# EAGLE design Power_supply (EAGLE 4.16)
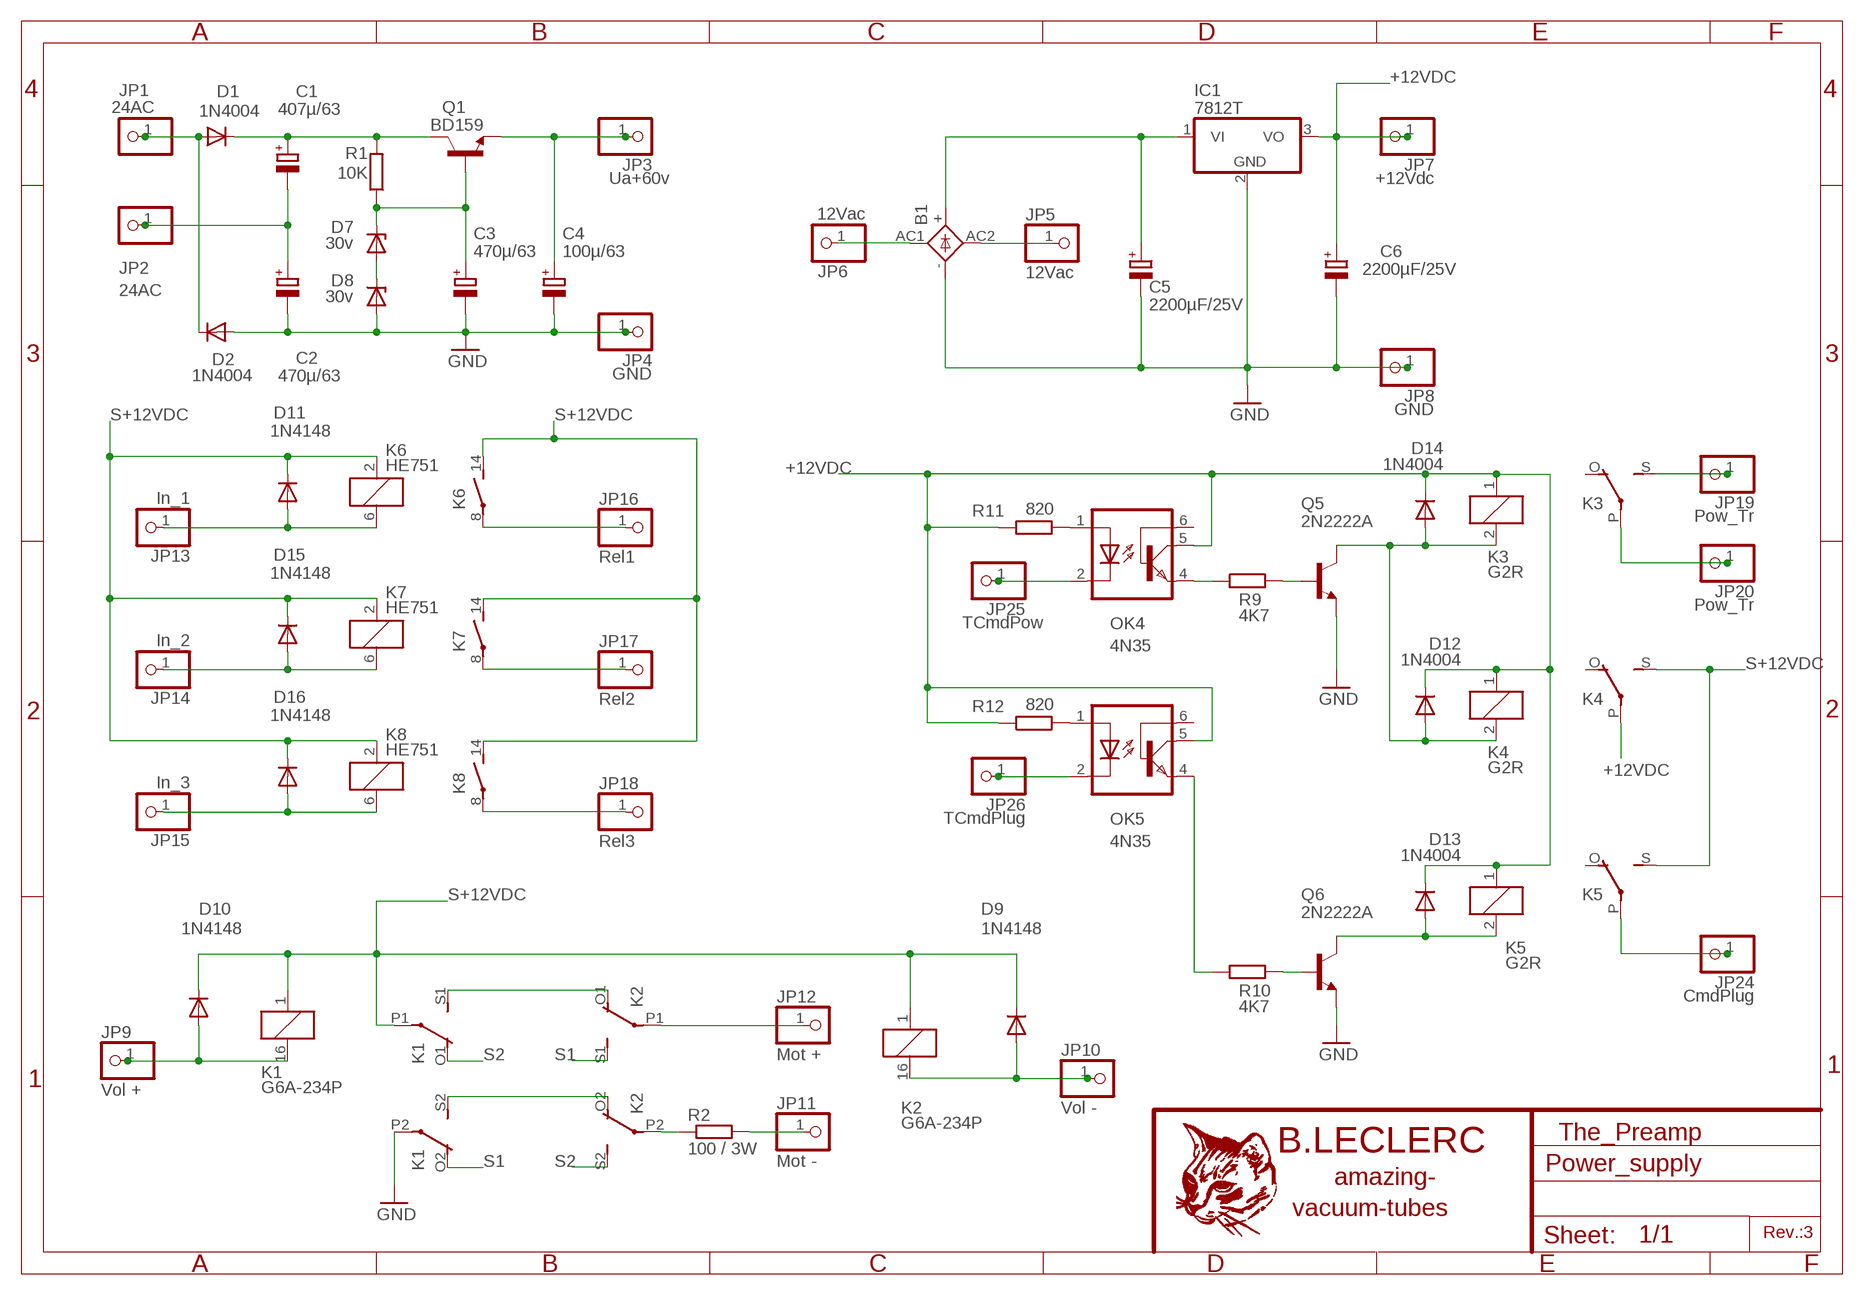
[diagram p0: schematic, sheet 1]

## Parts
B1  FB32  [FB32]
C1  407µ/63  CPOL-EUE7.5-16  [E7,5-16]
C2  470µ/63  CPOL-EUE7.5-16  [E7,5-16]
C3  470µ/63  CPOL-EUE7.5-16  [E7,5-16]
C4  100µ/63  CPOL-EUE5-10.5  [E5-10,5]
C5  2200µF/25V  CPOL-EUE7.5-18  [E7,5-18]
C6  2200µF/25V  CPOL-EUE7.5-18  [E7,5-18]
D1  1N4004  [DO41-10]
D2  1N4004  [DO41-10]
D7  30v  ZENER-DIODEZD-7.5  [ZDIO-7.5]
D8  30v  ZENER-DIODEZD-7.5  [ZDIO-7.5]
D9  1N4148  [DO35-10]
D10  1N4148  [DO35-10]
D11  1N4148  [DO35-10]
D12  1N4004  [DO41-10]
D13  1N4004  [DO41-10]
D14  1N4004  [DO41-10]
D15  1N4148  [DO35-10]
D16  1N4148  [DO35-10]
IC1  7812T  [TO220H]
JP1  24AC  PINHD-1X1  [1X01]
JP2  24AC  PINHD-1X1  [1X01]
JP3  Ua+60v  PINHD-1X1  [1X01]
JP4  GND  PINHD-1X1  [1X01]
JP5  12Vac  PINHD-1X1  [1X01]
JP6  12Vac  PINHD-1X1  [1X01]
JP7  +12Vdc  PINHD-1X1  [1X01]
JP8  GND  PINHD-1X1  [1X01]
JP9  Vol +  PINHD-1X1  [1X01]
JP10  Vol -  PINHD-1X1  [1X01]
JP11  Mot -  PINHD-1X1  [1X01]
JP12  Mot +  PINHD-1X1  [1X01]
JP13  In_1  PINHD-1X1  [1X01]
JP14  In_2  PINHD-1X1  [1X01]
JP15  In_3  PINHD-1X1  [1X01]
JP16  Rel1  PINHD-1X1  [1X01]
JP17  Rel2  PINHD-1X1  [1X01]
JP18  Rel3  PINHD-1X1  [1X01]
JP19  Pow_Tr  PINHD-1X1  [1X01]
JP20  Pow_Tr  PINHD-1X1  [1X01]
JP24  CmdPlug  PINHD-1X1  [1X01]
JP25  TCmdPow  PINHD-1X1  [1X01]
JP26  TCmdPlug  PINHD-1X1  [1X01]
K1  G6A-234P  [G6A-234P]
K2  G6A-234P  [G6A-234P]
K3  G2R  [G2R]
K4  G2R  [G2R]
K5  G2R  [G2R]
K6  HE751  [HE751]
K7  HE751  [HE751]
K8  HE751  [HE751]
OK4  4N35  [DIL06]
OK5  4N35  [DIL06]
Q1  BD159  MJE182  [TO225AA]
Q5  2N2222A  [TO18]
Q6  2N2222A  [TO18]
R1  10K  R-EU_0207/10  [0207/10]
R2  100 / 3W  R-EU_0613/15  [P0613/15]
R9  4K7  R-EU_0309/10  [0309/10]
R10  4K7  R-EU_0309/10  [0309/10]
R11  820  R-EU_0309/10  [0309/10]
R12  820  R-EU_0309/10  [0309/10]

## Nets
+12VDC: C6.+ D12.C D13.C D14.C IC1.3(VO) JP7.1 K3.1 K4.1 K4.P(2:P) K5.1 OK4.5(COL) OK5.5(COL) R11.1 R12.1
GND: B1.- C2.- C3.- C4.- C5.- C6.- D2.A D8.A IC1.2(GND) JP4.1 JP8.1 K1.P2(3:P) Q5.1(E) Q6.1(E)
N$1: D1.A D2.C JP1.1
N$2: C1.- C2.+ JP2.1
N$3: C1.+ D1.C Q1.2(C) R1.2
N$4: D7.A D8.C
N$5: C3.+ D7.C Q1.3(B) R1.1
N$6: B1.AC2 JP5.1
N$7: C4.+ JP3.1 Q1.1(E)
N$8: B1.AC1 JP6.1
N$9: B1.+ C5.+ IC1.1(VI)
N$10: K1.S1(2:S) K2.O1(2:O)
N$11: K1.S2(3:S) K2.O2(3:O)
N$12: JP12.1 K2.P1(2:P)
N$13: D10.A JP9.1 K1.16
N$14: K2.P2(3:P) R2.1
N$15: D9.A JP10.1 K2.16
N$16: JP11.1 R2.2
N$17: D11.A JP13.1 K6.6
N$18: JP16.1 K6.8(2:P)
N$19: JP17.1 K7.8(2:P)
N$20: JP18.1 K8.8(2:P)
N$21: D15.A JP14.1 K7.6
N$22: D16.A JP15.1 K8.6
N$32: JP19.1 K3.S(2:S)
N$35: JP24.1 K5.P(2:P)
N$37: JP20.1 K3.P(2:P)
N$38: D12.A D14.A K3.2 K4.2 Q5.3(C)
N$39: OK4.1(A) R11.2
N$40: D13.A K5.2 Q6.3(C)
N$41: OK5.1(A) R12.2
N$42: Q5.2(B) R9.2
N$43: OK4.4(EMI) R9.1
N$44: OK5.4(EMI) R10.1
N$45: Q6.2(B) R10.2
N$47: JP25.1 OK4.2(C)
N$48: JP26.1 OK5.2(C)
S1: K1.O2(3:O) K2.S1(2:S)
S2: K1.O1(2:O) K2.S2(3:S)
S+12VDC: D9.C D10.C D11.C D15.C D16.C K1.1 K1.P1(2:P) K2.1 K4.S(2:S) K5.S(2:S) K6.2 K6.14(2:S) K7.2 K7.14(2:S) K8.2 K8.14(2:S)
Unconnected: K3.O(2:O) K4.O(2:O) K5.O(2:O) OK4.6(BAS) OK5.6(BAS)

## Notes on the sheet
- The_Preamp
- Rev.:3

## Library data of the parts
B1 = rectifier:FB32: FAGOR RECTIFIER grid 1 x 10,2 x 7,5 mm
C1-C6 = rcl:CPOL-EU: POLARIZED CAPACITOR, European symbol
D1 D2 D12-D14 = diode:1N4004: DIODE
D7 D8 = diode:ZENER-DIODE: Z-Diode
D9-D11 D15 D16 = diode:1N4148: DIODE
IC1 = linear:78*: Positive VOLTAGE REGULATOR Source: http://cache.national.com/ds/LM/LM78L05.pdf http://www.fairchildsemi.com/ds/LM/LM7805.pdf
JP1-JP20 JP24-JP26 = pinhead:PINHD-1X1: PIN HEADER
K1 K2 = relay:G6A-234P: RELAY 2 x switch, 0.3 A/125 V AC, 1 A/30 V DC, Omron
K3-K5 = relay:G2R: RELAY 1 x switch, Omron
K6-K8 = relay:HE751: RELAY reed, 1 x norm. open, Hamlin
OK4 OK5 = optocoupler:4N35: MOTOROLA OPTO COUPLER
Q1 = transistor-npn:MJE182*: NPN Transistor
Q5 Q6 = transistor-npn:2N2222*: NPN Transistor
R1 R2 R9-R12 = rcl:R-EU_: RESISTOR, European symbol

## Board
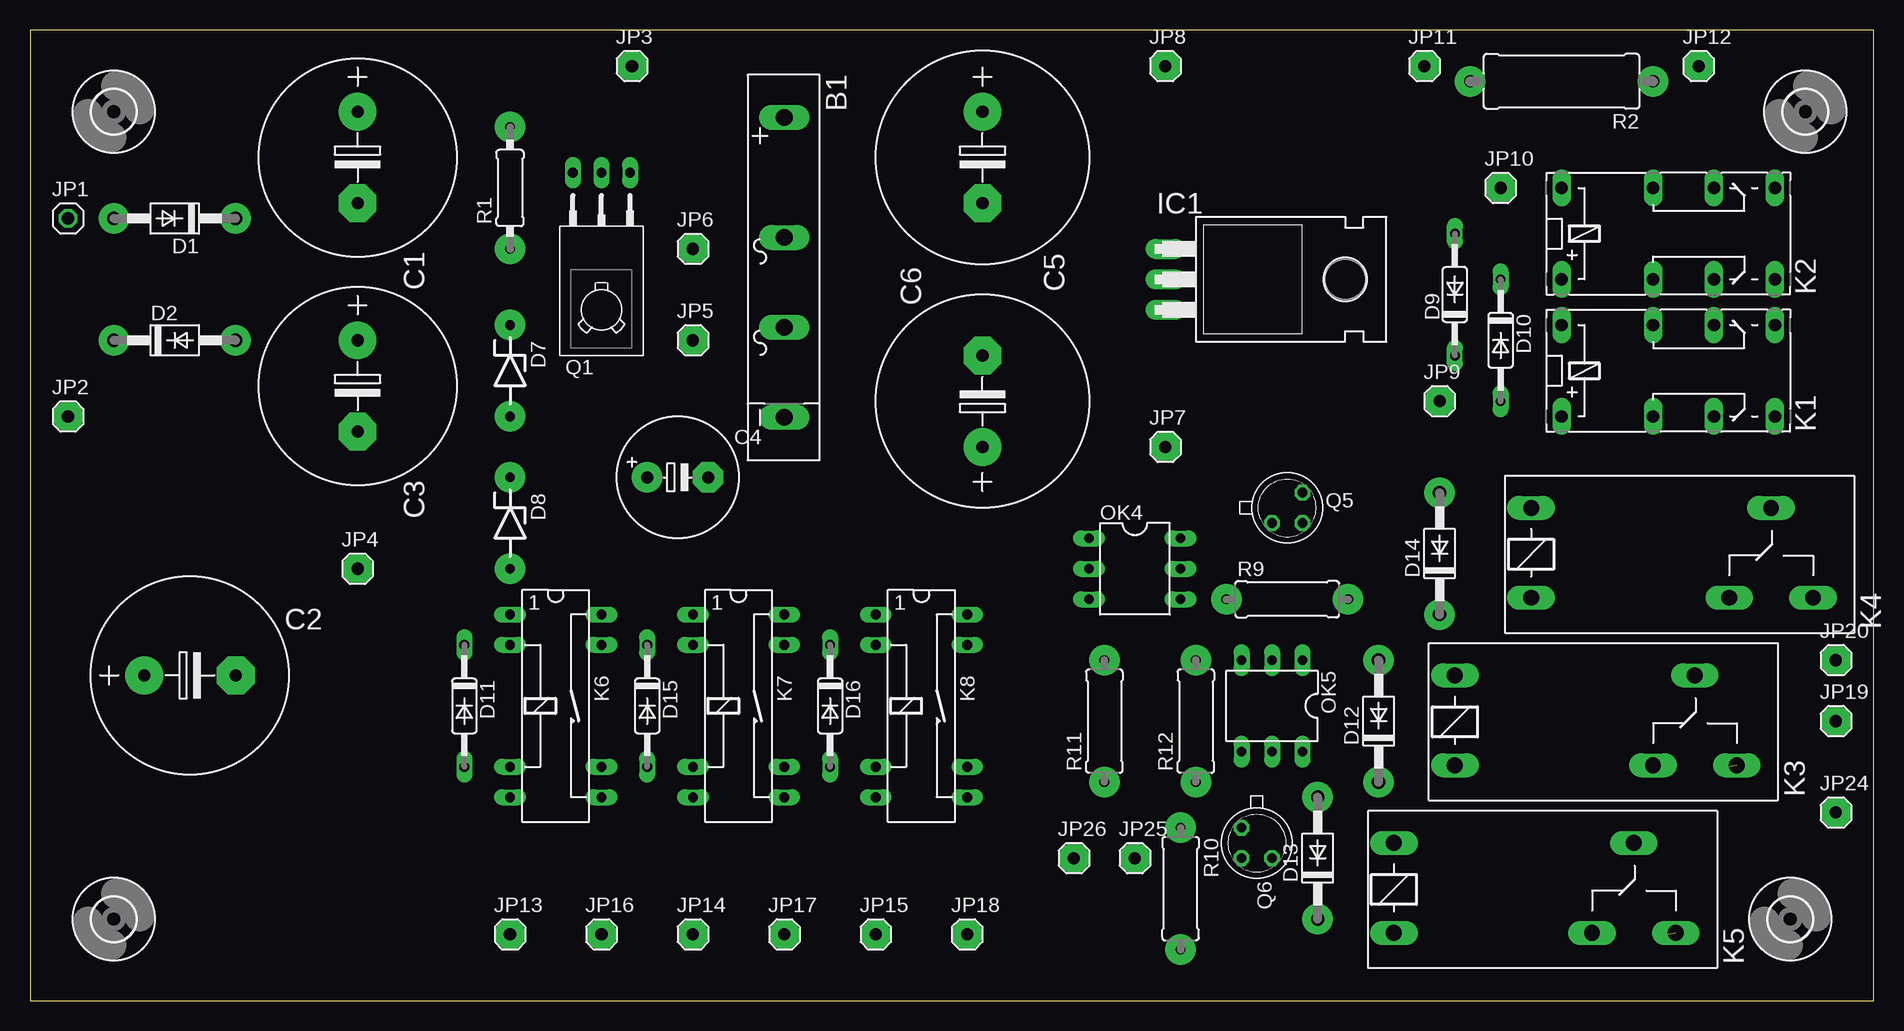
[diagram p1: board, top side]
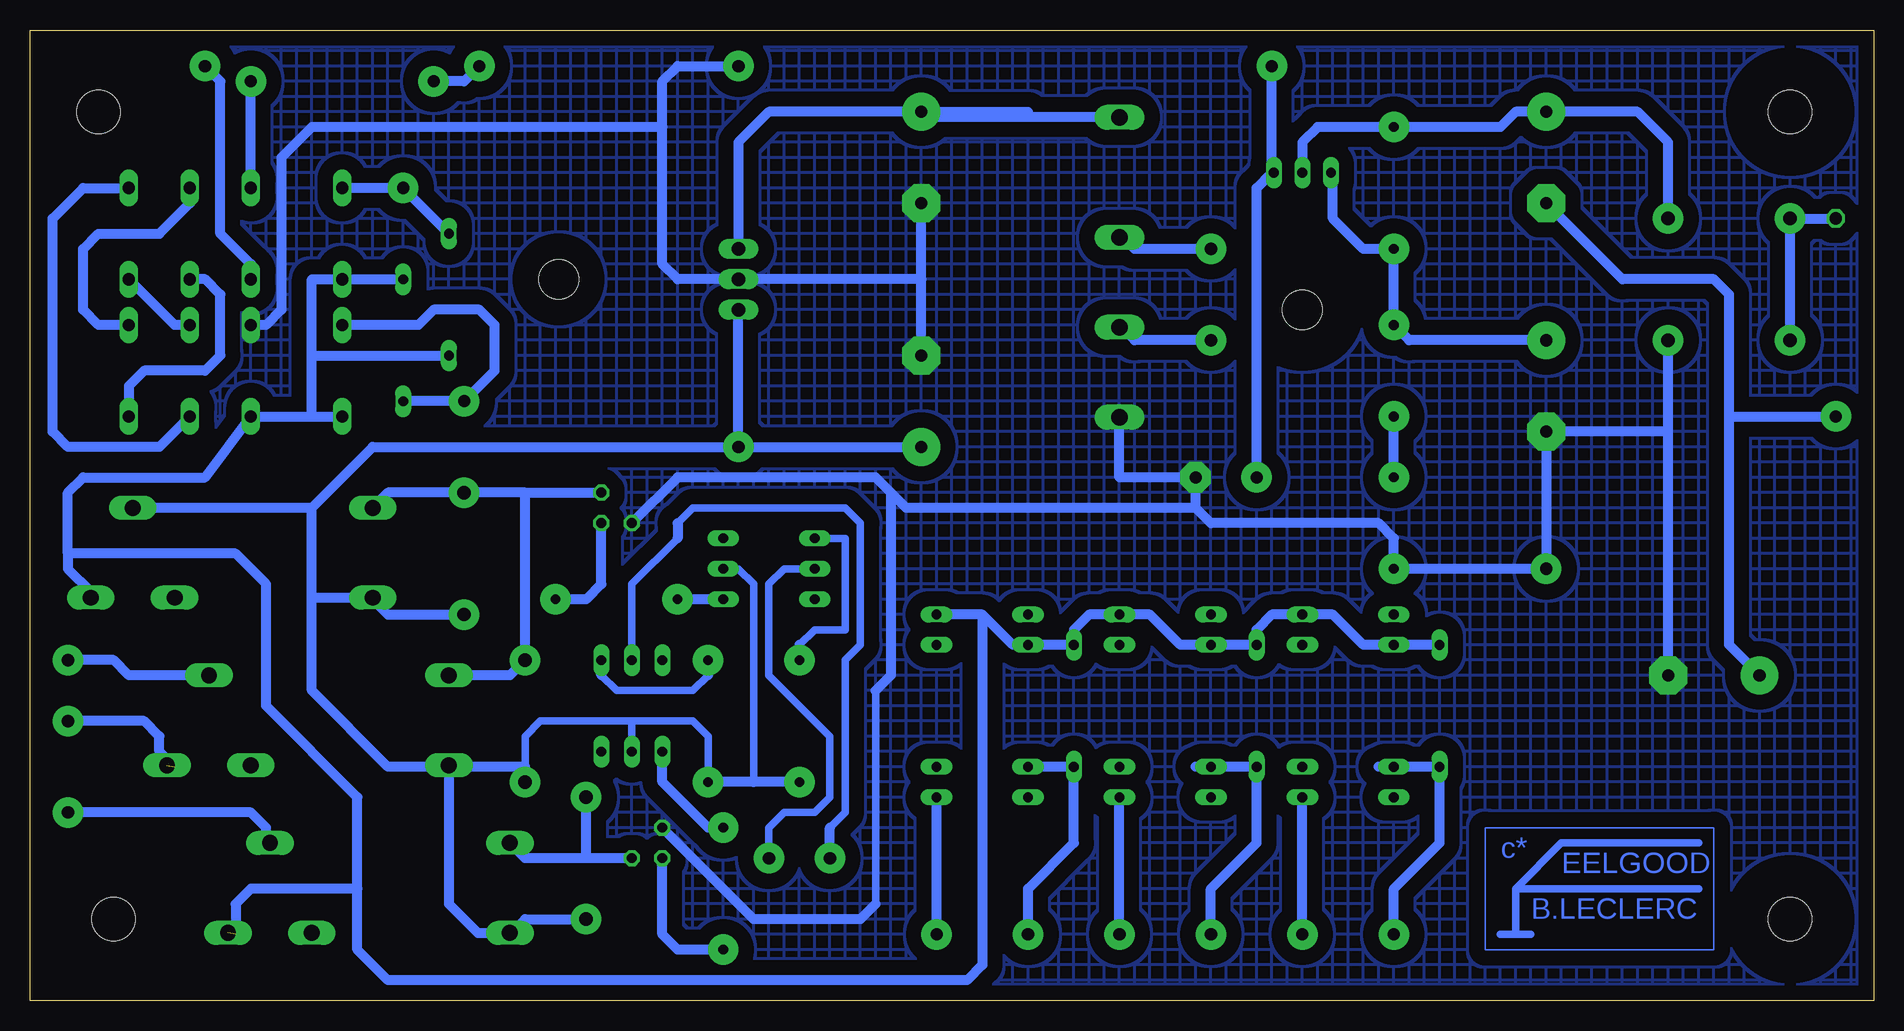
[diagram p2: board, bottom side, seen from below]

Size 153.65 x 80.95 mm. Coordinates in mm from the lower left corner, seen from the top.
Outline: 0,0 153.65,0 153.65,80.95 0,80.95 0,0
Copper layers (1*16): Top 0.035mm / dielectric 1.5mm / Bottom 0.035mm
Design rules "default": minimum track width 10mil, minimum drill 24mil, track to track 8mil, track to pad 8mil, pad to pad 8mil, via to via 8mil, smd to smd 8mil, copper to edge 40mil, drill to drill 8mil, minimum pad ring 10mil, minimum via ring 8mil, stop-mask expansion 4mil, vias tented up to drill 0mil, thermal gap 10mil

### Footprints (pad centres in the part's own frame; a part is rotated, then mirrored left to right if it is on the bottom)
FB32 = drill 1.397 long: + -13.5,0; - 11.494,0; AC1 -3.492,0; AC2 4.001,0
E7,5-16 = drill 1.016 pad 3.15 round: + -3.81,0 | drill 1.016 pad 3.15 octagon: - 3.81,0
E5-10,5 = drill 1.016 pad 2.54 round: + -2.54,0 | drill 1.016 pad 2.54 octagon: - 2.54,0
E7,5-18 = drill 1.016 pad 3.15 round: + -3.81,0 | drill 1.016 pad 3.15 octagon: - 3.81,0
DO41-10 = drill 1.118 round: A 5.08,0; C -5.08,0
ZDIO-7.5 = drill 0.813 octagon: A 3.81,0; C -3.81,0
DO35-10 = drill 0.813 long: A 5.08,0; C -5.08,0
TO220H = drill 1.118 long: 1 -2.54,-10.16; 2 0,-10.16; 3 2.54,-10.16 | hole 3.302: 0,4.826
1X01 = drill 1.016 octagon: 1 0,0
G6A-234P = drill 1.016 long: 1 -3.81,-3.81; 16 -3.81,3.81; O1 8.89,-3.81; O2 8.89,3.81; P1 3.81,-3.81; P2 3.81,3.81; S1 13.97,-3.81; S2 13.97,3.81
G2R = drill 1.321 long: 1 -2.54,-3.683; 2 -2.54,3.81; O 13.97,-3.683; P 17.45,3.81; S 20.955,-3.683
HE751 = drill 0.813 long: 1 -7.62,-3.81; 2 -5.08,-3.81; 6 5.08,-3.81; 7 7.62,-3.81; 8 7.62,3.81; 9 5.08,3.81; 13 -5.08,3.81; 14 -7.62,3.81
DIL06 = drill 0.813 long: 1 -2.54,-3.81; 2 0,-3.81; 3 2.54,-3.81; 4 2.54,3.81; 5 0,3.81; 6 -2.54,3.81
TO225AA = drill 0.813 long: 1 -2.381,-11.43; 2 0,-11.43; 3 2.381,-11.43 | hole 3.302: 0,0
TO18 = drill 0.813 octagon: 1 -1.27,-1.27; 2 1.27,-1.27; 3 1.27,1.27
0207/10 = drill 0.813 octagon: 1 -5.08,0; 2 5.08,0
P0613/15 = drill 1.016 octagon: 1 -7.62,0; 2 7.62,0
0309/10 = drill 0.813 octagon: 1 -5.08,0; 2 5.08,0
3,6 = hole 3.6: 0,0

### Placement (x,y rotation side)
B1  62.86,60.16 270 top
C1  27.3,70.32 270 top
C2  13.33,27.14 0 top
C3  27.3,51.27 270 top
C4  53.97,43.65 0 top
C5  79.37,70.32 270 top
C6  79.37,50 90 top
D1  12.06,65.24 180 top
D2  12.06,55.08 0 top
D7  40,52.54 270 top
D8  40,39.84 270 top
D9  118.74,58.89 90 top
D10  122.55,55.08 270 top
D11  36.19,24.6 270 top
D12  112.39,23.33 90 top
D13  107.31,11.9 90 top
D14  117.47,37.3 90 top
D15  51.43,24.6 270 top
D16  66.67,24.6 270 top
IC1  104.77,60.16 270 top
JP1  3.17,65.24 0 top
JP2  3.17,48.73 0 top
JP3  50.16,77.94 0 top
JP4  27.3,36.03 0 top
JP5  55.24,55.08 0 top
JP6  55.24,62.7 0 top
JP7  94.61,46.19 0 top
JP8  94.61,77.94 0 top
JP9  117.47,50 0 top
JP10  122.55,67.78 0 top
JP11  116.2,77.94 0 top
JP12  139.06,77.94 0 top
JP13  40,5.55 0 top
JP14  55.24,5.55 0 top
JP15  70.48,5.55 0 top
JP16  47.62,5.55 0 top
JP17  62.86,5.55 0 top
JP18  78.1,5.55 0 top
JP19  150.49,23.33 0 top
JP20  150.49,28.41 0 top
JP24  150.49,15.71 0 top
JP25  92.07,11.9 0 top
JP26  86.99,11.9 0 top
K1  131.44,52.54 0 top
K2  131.44,63.97 0 top
K3  121.28,23.33 0 top
K4  127.63,37.3 0 top
K5  116.2,9.36 0 top
K6  43.81,24.6 270 top
K7  59.05,24.6 270 top
K8  74.29,24.6 270 top
OK4  92.07,36.03 270 top
OK5  103.5,24.6 180 top
Q1  47.62,57.62 180 top
Q5  104.77,41.11 0 top
Q6  102.23,13.17 270 top
R1  40,67.78 90 top
R2  127.63,76.67 180 top
R9  104.77,33.49 0 top
R10  95.88,9.36 270 top
R11  89.53,23.33 90 top
R12  97.15,23.33 90 top
U$2  [3,6]  6.98,6.82 0 top
U$3  [3,6]  146.68,6.82 0 top
U$4  [3,6]  6.98,74.13 0 top
U$5  [3,6]  147.95,74.13 0 top
U$6  [LITTFEEL]  29.84,1.74 0 bottom

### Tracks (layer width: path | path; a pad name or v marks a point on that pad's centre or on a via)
+12VDC
  Bottom 0.61: R12.1 97.15,22.06 98.42,23.33 103.5,23.33 | 103.5,23.33 111.12,23.33 112.39,22.06 D12.C | 103.5,23.33 OK5.5 | OK4.5 94.61,36.03 93.34,34.76 93.34,18.25
  Bottom 0.813: JP7.1 IC1.3 | JP7.1 C6.+ | 130.17,41.11 K4.P | 130.17,41.11 125.09,46.19 JP7.1 | R11.1 93.34,18.25 R12.1 | 130.17,33.49 130.17,41.11 | 130.17,33.49 130.17,25.87 123.82,19.52 118.74,19.52 | D14.C 123.82,32.22 125.09,33.49 K4.1 130.04,33.62 130.17,33.49 | 118.74,19.52 112.39,19.52 D12.C | 118.74,19.52 K3.1 | 118.74,19.52 118.74,8.09 116.33,5.68 K5.1 113.66,5.55 112.39,6.82 D13.C
GND
  Bottom 0.61: 83.18,25.87 83.18,8.09
  Bottom 0.813: 17.14,47.46 D2.A | 17.14,47.46 C3.- JP4.1 D8.A 40,38.57 41.27,39.84 55.24,39.84 56.51,41.11 | C2.- 17.14,47.46 | C6.- 79.37,60.16 | 79.37,60.16 C5.- | 62.86,48.73 62.86,43.65 C4.- 56.51,41.11 | 79.37,60.16 IC1.2 99.69,60.16 100.96,61.43 100.96,72.86 | 100.96,72.86 100.96,76.67 99.69,77.94 JP8.1 | Q6.1 93.34,6.82 84.45,6.82 83.18,8.09 | 56.51,41.11 80.64,41.11 81.91,42.38 | Q5.1 99.69,43.65 83.18,43.65 81.91,42.38 | 81.91,42.38 81.91,27.14 83.18,25.87 | K1.P2 133.98,56.35 132.71,57.62 132.71,70.32 130.17,72.86 100.96,72.86
  pour Bottom (isolate 1.27, no thermals, hatched): 0.63,80.48 153.03,80.48 153.03,0.47 0.63,0.47
N$1
  Bottom 0.813: JP1.1 D1.A D2.C
N$2
  Bottom 0.813: 12.06,48.73 12.06,58.89 13.33,60.16 20.95,60.16 C1.- | 12.06,48.73 JP2.1 | 12.06,48.73 12.06,29.68 C2.+
N$3
  Bottom 0.813: D1.C 17.14,71.59 19.68,74.13 C1.+ 29.84,74.13 31.11,72.86 R1.2 46.35,72.86 47.62,71.59 Q1.2
N$4
  Bottom 0.813: D8.C D7.A
N$5
  Bottom 0.813: Q1.3 45.08,69.05 45.08,65.24 42.54,62.7 R1.1 D7.C 38.73,55.08 C3.+
N$6
  Bottom 0.813: B1.AC2 62.86,56.35 61.59,55.08 JP5.1
N$7
  Bottom 0.813: C4.+ 51.43,67.78 50.16,69.05 | 50.16,69.05 Q1.1 | 50.16,69.05 JP3.1
N$8
  Bottom 0.813: B1.AC1 62.86,63.97 61.59,62.7 JP6.1
N$9
  Bottom 0.813: C5.+ 70.48,74.13 | C5.+ 92.07,74.13 94.61,71.59 IC1.1 | B1.+ 79.37,73.66 C5.+
N$10
  Bottom 0.813: K2.O1 139.06,60.16 137.79,58.89 137.79,53.81 139.06,52.54 144.14,52.54 145.41,51.27 K1.S1
N$11
  Bottom 0.813: K2.O2 140.33,66.51 142.87,63.97 147.95,63.97 149.22,62.7 149.22,57.62 147.95,56.35 K1.S2
N$12
  Bottom 0.813: K2.P1 135.25,61.43 137.79,63.97 137.79,76.67 JP12.1
N$13
  Bottom 0.813: D10.A JP9.1 114.93,52.54 114.93,56.35 116.2,57.62 120.01,57.62 121.28,56.35 K1.16
N$14
  Bottom 0.813: K2.P2 R2.1
N$15
  Bottom 0.813: K2.16 JP10.1 D9.A
N$16
  Bottom 0.813: R2.2 117.47,76.67 JP11.1
N$17
  Bottom 0.813: 41.27,19.52 K6.6 D11.A 36.19,13.17 40,9.36 JP13.1
N$18
  Bottom 0.813: JP16.1 K6.8
N$19
  Bottom 0.813: JP17.1 K7.8
N$20
  Bottom 0.813: JP18.1 K8.8
N$21
  Bottom 0.813: 56.51,19.52 K7.6 D15.A 51.43,13.17 55.24,9.36 JP14.1
N$22
  Bottom 0.813: K8.6 D16.A 66.67,13.17 70.48,9.36 JP15.1
N$32  (1 unrouted)
  Bottom 0.813: JP19.1 144.14,23.33 142.87,22.06 142.87,20.79 141.6,19.52 142.87,19.52
N$35
  Bottom 0.813: JP24.1 135.25,15.71 133.98,14.44 133.98,13.17 K5.P
N$37
  Bottom 0.813: K3.P 145.41,27.14 146.68,28.41 JP20.1
N$38
  Bottom 0.813: 112.39,42.38 Q5.3 | 112.39,42.38 D14.A 123.82,42.38 K4.2 | K3.2 113.66,27.14 D12.A 112.39,42.38
N$39
  Bottom 0.61: OK4.1 85.72,38.57 85.72,30.95 88.26,30.95 89.53,29.68
  Bottom 0.813: 89.53,29.68 R11.2
N$40
  Bottom 0.813: Q6.3 107.31,11.9 | 107.31,11.9 112.39,11.9 K5.2 | 107.31,11.9 D13.A
N$41
  Bottom 0.61: 106.04,27.14 104.77,25.87 98.42,25.87 97.15,27.14
  Bottom 0.813: 106.04,27.14 OK5.1 | 97.15,27.14 R12.2
N$42
  Bottom 0.813: Q5.2 106.04,34.76 107.31,33.49 R9.2
N$43
  Bottom 0.813: OK4.4 R9.1
N$44
  Bottom 0.813: OK5.4 100.96,18.25 97.15,14.44 R10.1
N$45
  Bottom 0.813: Q6.2 100.96,5.55 99.69,4.28 R10.2
N$47
  Bottom 0.61: OK4.2 90.8,36.03 92.07,34.76 92.07,27.14 86.99,22.06 86.99,16.98 88.26,15.71 90.8,15.71 92.07,14.44 JP25.1
N$48
  Bottom 0.61: OK5.2 103.5,34.76 99.69,38.57 | 99.69,39.84 98.42,41.11 85.72,41.11 84.45,39.84 84.45,29.68 85.72,28.41 85.72,15.71 86.99,14.44
  Bottom 0.813: 99.69,39.84 99.69,38.57 | JP26.1 86.99,14.44
N$56  (via drill 0.6 pad 2.54)
  other vias: 95.88,4.28
N$57  (via drill 0.6 pad 2.54)
  other vias: 95.88,14.44
N$58  (via drill 0.6 pad 2.54)
  other vias: 89.53,28.41
N$59  (via drill 0.6 pad 2.54)
  other vias: 89.53,18.25
N$60  (via drill 0.6 pad 2.54)
  other vias: 97.15,18.25
N$61  (via drill 0.6 pad 2.54)
  other vias: 97.15,28.41
N$62  (via drill 0.6 pad 2.54)
  other vias: 117.47,32.22
N$63  (via drill 0.6 pad 2.54)
  other vias: 112.39,18.25
N$64  (via drill 0.6 pad 2.54)
  other vias: 107.31,16.98
N$65  (via drill 0.6 pad 2.54)
  other vias: 107.31,6.82
N$66  (via drill 0.6 pad 2.54)
  other vias: 112.39,28.41
N$67  (via drill 0.6 pad 2.54)
  other vias: 117.47,42.38
N$68  (via drill 0.6 pad 2.54)
  other vias: 109.85,33.49
N$69  (via drill 0.6 pad 2.54)
  other vias: 99.69,33.49
N$70  (via drill 0.6 pad 2.54)
  other vias: 40,56.35
N$71  (via drill 0.6 pad 2.54)
  other vias: 40,72.86
N$74  (via drill 0.6 pad 2.54)
  other vias: 17.14,55.08
N$75  (via drill 0.6 pad 2.54)
  other vias: 135.25,76.67
N$76  (via drill 0.6 pad 2.54)
  other vias: 40,36.03
N$77  (via drill 0.6 pad 2.54)
  other vias: 120.01,76.67
N$84  (via drill 0.6 pad 2.54)
  other vias: 40,62.7
N$85  (via drill 0.6 pad 2.54)
  other vias: 40,48.73
N$86  (via drill 0.6 pad 2.54)
  other vias: 40,43.65
N$88  (via drill 0.6 pad 2.54)
  other vias: 17.14,65.24
N$89  (via drill 0.6 pad 2.54)
  other vias: 6.98,55.08
N$90  (via drill 0.6 pad 2.54)
  other vias: 6.98,65.24
N$91  (via drill 0.6 pad 2.54)
  other vias: 3.17,48.73
N$92  (via drill 0.6 pad 2.54)
  other vias: 27.3,36.03
N$93  (via drill 0.6 pad 2.54)
  other vias: 50.16,77.94
N$94  (via drill 0.6 pad 2.54)
  other vias: 55.24,55.08
N$95  (via drill 0.6 pad 2.54)
  other vias: 55.24,62.7
N$96  (via drill 0.6 pad 2.54)
  other vias: 94.61,77.94
N$97  (via drill 0.6 pad 2.54)
  other vias: 116.2,77.94
N$98  (via drill 0.6 pad 2.54)
  other vias: 139.06,77.94
N$99  (via drill 0.6 pad 2.54)
  other vias: 122.55,67.78
N$100  (via drill 0.6 pad 2.54)
  other vias: 117.47,50
N$101  (via drill 0.6 pad 2.54)
  other vias: 150.49,28.41
N$102  (via drill 0.6 pad 2.54)
  other vias: 150.49,23.33
N$103  (via drill 0.6 pad 2.54)
  other vias: 150.49,15.71
N$104  (via drill 0.6 pad 2.54)
  other vias: 62.86,5.55
N$105  (via drill 0.6 pad 2.54)
  other vias: 78.1,5.55
N$106  (via drill 0.6 pad 2.54)
  other vias: 86.99,11.9
N$107  (via drill 0.6 pad 2.54)
  other vias: 92.07,11.9
N$108  (via drill 0.6 pad 2.54)
  other vias: 94.61,46.19
N$109  (via drill 0.6 pad 2.54)
  other vias: 40,5.55
N$110  (via drill 0.6 pad 2.54)
  other vias: 55.24,5.55
N$111  (via drill 0.6 pad 2.54)
  other vias: 47.62,5.55
N$112  (via drill 0.6 pad 2.54)
  other vias: 70.48,5.55
S1
  Bottom 0.813: K2.S1 141.6,56.35 K1.O2
S2
  Bottom 0.813: K2.S2 149.22,67.78 151.76,65.24 151.76,47.46 150.49,46.19 142.87,46.19 K1.O1
S+12VDC  (1 unrouted)
  Bottom 0.813: K4.S 148.59,34.12 150.49,36.03 150.49,37.3 | 150.49,37.3 150.49,42.38 149.22,43.65 139.06,43.65 K1.P1 130.17,48.73 | 130.17,48.73 K1.1 | 130.17,48.73 130.17,53.81 | D10.C K2.1 130.17,60.16 130.17,53.81 | 130.17,53.81 D9.C | 150.49,37.3 136.52,37.3 133.98,34.76 133.98,24.6 126.36,16.98 126.36,9.36 | 126.36,9.36 135.25,9.36 136.52,8.09 136.52,5.55 | D11.C K6.2 42.54,29.68 45.08,32.22 K6.14 50.16,32.22 51.43,30.95 D15.C K7.2 57.78,29.68 60.32,32.22 K7.14 65.4,32.22 66.67,30.95 D16.C K8.2 71.75,29.68 74.29,32.22 | 74.29,32.22 K8.14 | 74.29,32.22 74.29,3.01 75.56,1.74 123.82,1.74 126.36,4.28 126.36,9.36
